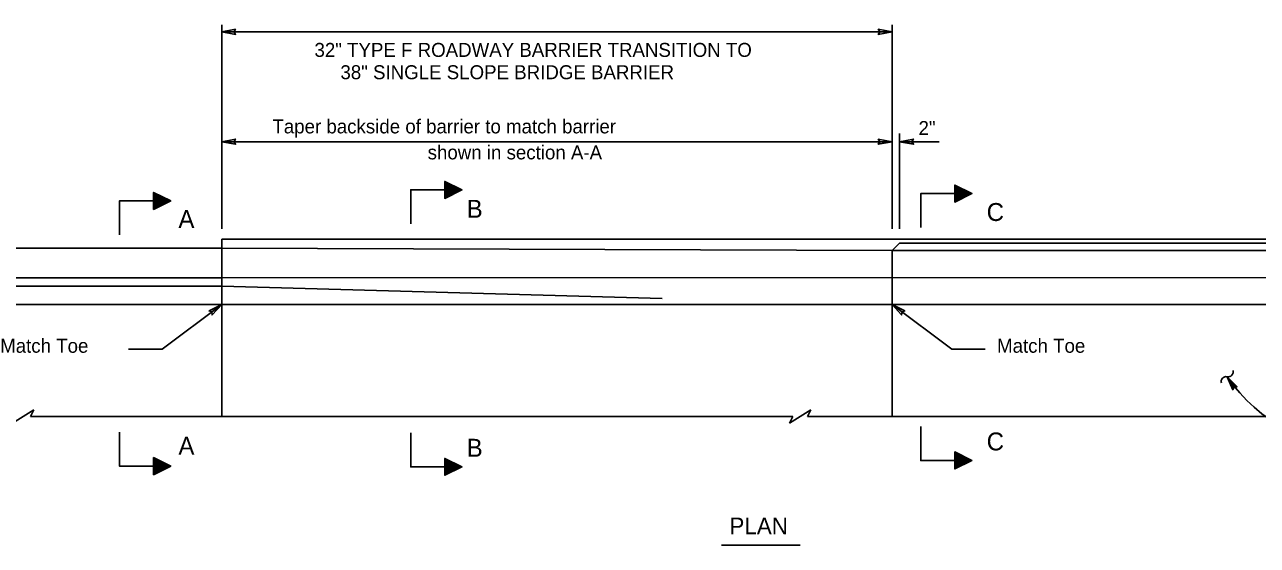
# Model space of a CAD drawing. Extents: x 0 to 2.83, y -0.03 to 1.83.
# Drawn here: x 0.699 to 1.848, y 0.72 to 1.206 of the extents above; entities that cross this region are included whole.
import ezdxf

# ---------------------------------------------------------------- set-up
doc = ezdxf.new("R2010")
doc.units = 0
for name, color, linetype in [('40', 7, 'Continuous'), ('50', 7, 'Continuous'), ('54', 7, 'Continuous'), ('55', 7, 'Continuous'), ('57', 7, 'Continuous')]:
    doc.layers.add(name, color=color, linetype=linetype)

msp = doc.modelspace()

# ---------------------------------------------------------------- linework, layer by layer
at = {"layer": '40'}
for p, q in [((0.2743, 0.9973), (0.8822, 0.9973)), ((0.2743, 0.9696), (0.8822, 0.9696)), ((0.2743, 0.9618), (0.8822, 0.9618)), ((0.2743, 0.9448), (0.8822, 0.9448)), ((0.8822, 0.9448), (0.8822, 0.8407))]:
    msp.add_line(p, q, dxfattribs=at)
at = {"layer": '50'}
for p, q in [((0.8822, 1.0056), (1.9702, 1.0056)), ((0.8822, 0.9448), (0.8822, 1.0056)), ((1.5141, 1.0021), (1.5071, 0.9951)), ((1.5141, 1.0021), (1.9702, 1.0021)), ((1.5071, 0.9951), (0.8822, 0.9973)), ((1.5072, 0.9448), (1.5072, 0.9951)), ((1.5072, 0.9951), (1.9702, 0.9951)), ((0.8822, 0.9696), (1.9736, 0.97)), ((0.8822, 0.9618), (1.2929, 0.9506)), ((0.8822, 0.9448), (1.9702, 0.9448)), ((1.5072, 0.9448), (1.5072, 0.8405))]:
    msp.add_line(p, q, dxfattribs=at)
at = {"layer": '54'}
for points in [[(0.8822, 1.199), (0.8952, 1.1966), (0.8937, 1.199), (0.895, 1.2014)], [(0.8822, 1.199), (0.8952, 1.1966), (0.8937, 1.199), (0.895, 1.2014)], [(0.8822, 1.199), (0.8952, 1.1966), (0.8937, 1.199), (0.895, 1.2014)], [(1.5072, 1.199), (1.4942, 1.2013), (1.4957, 1.199), (1.4943, 1.1966)], [(1.5072, 1.199), (1.4942, 1.2013), (1.4957, 1.199), (1.4943, 1.1966)], [(1.5072, 1.199), (1.4942, 1.2013), (1.4957, 1.199), (1.4943, 1.1966)], [(0.8822, 1.0966), (0.8952, 1.0942), (0.8937, 1.0966), (0.895, 1.099)], [(0.8822, 1.0966), (0.8952, 1.0942), (0.8937, 1.0966), (0.895, 1.099)], [(0.8822, 1.0966), (0.8952, 1.0942), (0.8937, 1.0966), (0.895, 1.099)], [(1.5072, 1.0966), (1.4942, 1.0989), (1.4957, 1.0966), (1.4943, 1.0942)], [(1.5141, 1.0966), (1.5271, 1.0942), (1.5256, 1.0966), (1.527, 1.099)], [(0.8822, 0.9448), (0.8704, 0.9389), (0.873, 0.9379), (0.8733, 0.9352)], [(0.8822, 0.9448), (0.8704, 0.9389), (0.873, 0.9379), (0.8733, 0.9352)], [(0.8822, 0.9448), (0.8704, 0.9389), (0.873, 0.9379), (0.8733, 0.9352)], [(1.5072, 0.9448), (1.519, 0.9389), (1.5164, 0.9379), (1.516, 0.9352)]]:
    msp.add_lwpolyline(points, close=True, dxfattribs=at)
at = {"layer": '55'}
for p, q in [((0.8822, 1.0453), (0.8822, 1.2056)), ((1.5072, 1.199), (0.8822, 1.199)), ((1.5072, 1.199), (0.8822, 1.199)), ((1.5072, 1.199), (0.8822, 1.199)), ((1.5072, 1.0155), (1.5072, 1.2056)), ((0.8822, 1.0155), (0.8822, 1.1274)), ((0.8822, 1.0286), (0.8822, 1.1274)), ((0.8822, 1.0286), (0.8822, 1.1274)), ((0.8822, 1.0286), (0.8822, 1.1274)), ((1.5072, 1.0286), (1.5072, 1.1337)), ((1.5072, 1.0286), (1.5072, 1.1337)), ((1.5072, 1.0286), (1.5072, 1.1337)), ((1.5072, 1.0286), (1.5072, 1.1337)), ((1.5141, 1.0155), (1.5141, 1.1041)), ((1.5072, 1.0966), (0.8822, 1.0966)), ((1.4994, 1.0966), (0.8822, 1.0966)), ((1.4994, 1.0966), (0.8822, 1.0966)), ((1.5141, 1.0966), (1.551, 1.0966)), ((0.6871, 0.8343), (0.707, 0.8466)), ((0.7039, 0.8404), (0.707, 0.8466)), ((0.7039, 0.8404), (0.7198, 0.8404)), ((0.7078, 0.8405), (1.4038, 0.8405)), ((1.3986, 0.8404), (1.4145, 0.8404)), ((1.4114, 0.8343), (1.4313, 0.8466)), ((1.4114, 0.8343), (1.4145, 0.8404)), ((1.4282, 0.8404), (1.4313, 0.8466)), ((1.4282, 0.8404), (1.4441, 0.8404)), ((1.432, 0.8405), (2.0686, 0.8405))]:
    msp.add_line(p, q, dxfattribs=at)
for points in [[(1.0585, 1.02), (1.0585, 1.0518), (1.0902, 1.0518), (1.0902, 1.0596), (1.1061, 1.0517), (1.0902, 1.0437), (1.0902, 1.0517), (1.0914, 1.0518), (1.0914, 1.058), (1.1041, 1.0517), (1.0914, 1.0453), (1.0914, 1.0517), (1.0923, 1.0518), (1.0923, 1.0567), (1.1025, 1.0516), (1.0923, 1.0466), (1.0923, 1.0517), (1.0933, 1.0518), (1.0933, 1.0553), (1.1004, 1.0517), (1.0933, 1.0481), (1.0933, 1.0517), (1.0943, 1.0518), (1.0943, 1.0542), (1.0993, 1.0517), (1.0943, 1.0492), (1.0943, 1.0517), (1.0949, 1.0518), (1.0949, 1.0532), (1.0978, 1.0517), (1.0949, 1.0503), (1.0949, 1.0517), (1.0954, 1.0518), (1.0954, 1.0523), (1.0965, 1.0518), (1.0954, 1.0512), (1.0954, 1.0517)], [(0.7871, 1.0097), (0.7871, 1.0415), (0.8188, 1.0415), (0.8188, 1.0493), (0.8347, 1.0414), (0.8188, 1.0335), (0.8188, 1.0414), (0.82, 1.0415), (0.82, 1.0477), (0.8327, 1.0414), (0.82, 1.035), (0.82, 1.0414), (0.8209, 1.0415), (0.8209, 1.0464), (0.8311, 1.0414), (0.8209, 1.0363), (0.8209, 1.0414), (0.8219, 1.0415), (0.8219, 1.045), (0.829, 1.0414), (0.8219, 1.0379), (0.8219, 1.0414), (0.8229, 1.0415), (0.8229, 1.044), (0.8279, 1.0414), (0.8229, 1.0389), (0.8229, 1.0414), (0.8235, 1.0415), (0.8235, 1.0429), (0.8264, 1.0414), (0.8235, 1.04), (0.8235, 1.0414), (0.824, 1.0415), (0.824, 1.042), (0.8251, 1.0415), (0.824, 1.0409), (0.824, 1.0414)], [(1.5339, 1.0166), (1.5339, 1.0483), (1.5656, 1.0483), (1.5656, 1.0562), (1.5815, 1.0483), (1.5656, 1.0403), (1.5656, 1.0482), (1.5668, 1.0483), (1.5668, 1.0546), (1.5795, 1.0482), (1.5668, 1.0419), (1.5668, 1.0482), (1.5678, 1.0483), (1.5678, 1.0533), (1.5779, 1.0482), (1.5678, 1.0431), (1.5678, 1.0482), (1.5687, 1.0483), (1.5687, 1.0519), (1.5759, 1.0483), (1.5687, 1.0447), (1.5687, 1.0482), (1.5697, 1.0483), (1.5697, 1.0508), (1.5747, 1.0483), (1.5697, 1.0458), (1.5697, 1.0482), (1.5703, 1.0483), (1.5703, 1.0498), (1.5732, 1.0483), (1.5703, 1.0468), (1.5703, 1.0482), (1.5708, 1.0483), (1.5708, 1.0489), (1.5719, 1.0483), (1.5708, 1.0478), (1.5708, 1.0482)], [(0.7954, 0.9032), (0.8266, 0.9032), (0.8822, 0.9448)], [(1.5939, 0.9032), (1.5628, 0.9032), (1.5072, 0.9448)], [(1.8195, 0.8776), (1.8287, 0.8682), (1.8265, 0.8681), (1.8211, 0.8751), (1.8256, 0.8675), (1.8247, 0.8655), (1.8195, 0.8776)], [(1.8226, 0.8739), (1.8264, 0.8688), (1.8275, 0.8688), (1.8203, 0.8764), (1.8246, 0.8668), (1.825, 0.8679), (1.8218, 0.873)], [(1.5339, 0.8312), (1.5339, 0.7994), (1.5656, 0.7994), (1.5656, 0.7916), (1.5815, 0.7995), (1.5656, 0.8075), (1.5656, 0.7995), (1.5668, 0.7994), (1.5668, 0.7932), (1.5795, 0.7995), (1.5668, 0.8059), (1.5668, 0.7995), (1.5678, 0.7994), (1.5678, 0.7945), (1.5779, 0.7996), (1.5678, 0.8046), (1.5678, 0.7995), (1.5687, 0.7994), (1.5687, 0.7959), (1.5759, 0.7995), (1.5687, 0.8031), (1.5687, 0.7995), (1.5697, 0.7994), (1.5697, 0.797), (1.5747, 0.7995), (1.5697, 0.802), (1.5697, 0.7995), (1.5703, 0.7994), (1.5703, 0.798), (1.5732, 0.7995), (1.5703, 0.8009), (1.5703, 0.7995), (1.5708, 0.7994), (1.5708, 0.7989), (1.5719, 0.7994), (1.5708, 0.8), (1.5708, 0.7995)], [(0.7871, 0.8259), (0.7871, 0.7942), (0.8188, 0.7942), (0.8188, 0.7863), (0.8347, 0.7943), (0.8188, 0.8022), (0.8188, 0.7943), (0.82, 0.7942), (0.82, 0.7879), (0.8327, 0.7943), (0.82, 0.8006), (0.82, 0.7943), (0.8209, 0.7942), (0.8209, 0.7892), (0.8311, 0.7943), (0.8209, 0.7994), (0.8209, 0.7943), (0.8219, 0.7942), (0.8219, 0.7907), (0.829, 0.7942), (0.8219, 0.7978), (0.8219, 0.7943), (0.8229, 0.7942), (0.8229, 0.7917), (0.8279, 0.7942), (0.8229, 0.7967), (0.8229, 0.7943), (0.8235, 0.7942), (0.8235, 0.7927), (0.8264, 0.7942), (0.8235, 0.7957), (0.8235, 0.7943), (0.824, 0.7942), (0.824, 0.7936), (0.8251, 0.7942), (0.824, 0.7947), (0.824, 0.7943)], [(1.0585, 0.8253), (1.0585, 0.7935), (1.0902, 0.7935), (1.0902, 0.7857), (1.1061, 0.7936), (1.0902, 0.8015), (1.0902, 0.7936), (1.0914, 0.7935), (1.0914, 0.7873), (1.1041, 0.7936), (1.0914, 0.8), (1.0914, 0.7936), (1.0923, 0.7935), (1.0923, 0.7886), (1.1025, 0.7936), (1.0923, 0.7987), (1.0923, 0.7936), (1.0933, 0.7935), (1.0933, 0.79), (1.1004, 0.7936), (1.0933, 0.7972), (1.0933, 0.7936), (1.0943, 0.7935), (1.0943, 0.791), (1.0993, 0.7936), (1.0943, 0.7961), (1.0943, 0.7936), (1.0949, 0.7935), (1.0949, 0.7921), (1.0978, 0.7936), (1.0949, 0.795), (1.0949, 0.7936), (1.0954, 0.7935), (1.0954, 0.793), (1.0965, 0.7935), (1.0954, 0.7941), (1.0954, 0.7936)]]:
    msp.add_lwpolyline(points, dxfattribs=at)
for centre, radius, start, end in [((1.8186, 0.873), 0.0047, 78.7125, 195.1185), ((1.8204, 0.8822), 0.0047, 258.7125, 15.1185), ((1.9416, 0.96), 0.1473, 214.0105, 272.8594)]:
    msp.add_arc(centre, radius, start, end, dxfattribs=at)
at = {"layer": '57'}
msp.add_line((1.4215, 0.7205), (1.3481, 0.7205), dxfattribs=at)

# ---------------------------------------------------------------- texts
for s, height, p in [('32" TYPE F ROADWAY BARRIER TRANSITION TO ', 0.013021, (0.9687, 1.1756)), ('     38" SINGLE SLOPE BRIDGE BARRIER', 0.013021, (0.9687, 1.1548)), ('Taper backside of barrier to match barrier ', 0.013021, (0.9295, 1.1043)), ('2"', 0.01302, (1.5318, 1.1028)), ('shown in section A-A', 0.013021, (1.0742, 1.0801)), ('B', 0.0167, (1.1106, 1.0257)), ('C', 0.0167, (1.5953, 1.0227)), ('A', 0.0167, (0.8419, 1.0162)), ('Match Toe', 0.01302, (0.6757, 0.8999)), ('Match Toe', 0.01302, (1.605, 0.8999)), ('A', 0.0167, (0.8419, 0.8049)), ('B', 0.0167, (1.1106, 0.803)), ('C', 0.0167, (1.5953, 0.8089)), ('PLAN', 0.01562, (1.3555, 0.7307))]:
    msp.add_text(s, height=height, dxfattribs=at).set_placement(p)

doc.saveas('drawing.dxf')
